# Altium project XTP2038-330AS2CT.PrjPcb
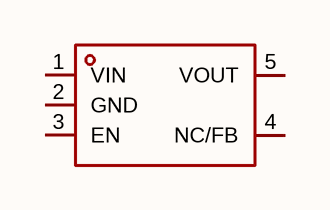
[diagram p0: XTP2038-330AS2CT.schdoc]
1 sheet, 1 parts. Net scope: global (net labels, ports and power ports of the same name join across sheets).

## Sheet XTP2038-330AS2CT.schdoc
size 127 x 101 mm

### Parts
U?  xtp2038-330as2ct  [SOT-23-5_L2.9-W1.6-P0.95-LS2.8-BR]  (value not drawn)

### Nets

Not connected (* = marked no-connect by the designer): U? 1(VIN) 2(GND) 3(EN) 4(NC/FB) 5(VOUT)

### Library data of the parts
U? = xtp2038-330as2ct: 输出极性:正极;工作电压:5.5V;输出电压:3.3V;输出电流:500mA;电源纹波抑制比(PSRR):-;输出类型:固定;; Manufacturer: XTX(芯天下); AddInBom: yes; ModelId: 7ba65df16e7b4570af156e925f9c37fe; ModelTransform: 114.173,114.173,0,90,0,0,0,0,0; Output Configuration: 正极; Voltage - Supply: 5.5V; Output Voltage: 3.3V; Output Current: 500mA; Voltage Dropout: 180mV@(300mA); standby current: 15uA; Output Type: 固定; Number of Outputs: 1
